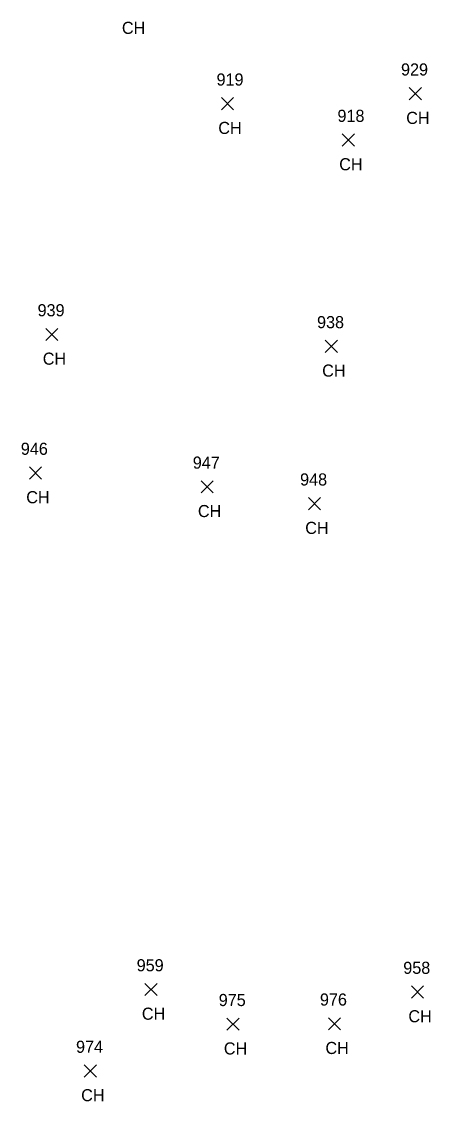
# Model space of a CAD drawing. Extents: x 1885914 to 1887218, y 756253 to 760620.
# Drawn here: x 1886670.4 to 1886738.1, y 759584.2 to 759762.6 of the extents above; entities that cross this region are included whole.
import ezdxf

# ---------------------------------------------------------------- set-up
doc = ezdxf.new("R2010")
doc.units = 0
for name, color, linetype in [('L_A', 7, 'Continuous'), ('L_I', 7, 'Continuous'), ('L_TIC', 7, 'Continuous')]:
    doc.layers.add(name, color=color, linetype=linetype)

msp = doc.modelspace()

# ---------------------------------------------------------------- linework, layer by layer
at = {"layer": 'L_TIC'}
for points in [[(1886734.56, 759749.69), (1886736.56, 759751.69)], [(1886736.56, 759749.69), (1886734.56, 759751.69)], [(1886703.49, 759748.03), (1886705.49, 759750.03)], [(1886705.49, 759748.03), (1886703.49, 759750.03)], [(1886723.48, 759742.03), (1886725.48, 759744.03)], [(1886725.48, 759742.03), (1886723.48, 759744.03)], [(1886674.45, 759709.92), (1886676.45, 759711.92)], [(1886676.45, 759709.92), (1886674.45, 759711.92)], [(1886720.66, 759707.95), (1886722.66, 759709.95)], [(1886722.66, 759707.95), (1886720.66, 759709.95)], [(1886671.72, 759687.04), (1886673.72, 759689.04)], [(1886673.72, 759687.04), (1886671.72, 759689.04)], [(1886700.12, 759684.75), (1886702.12, 759686.75)], [(1886702.12, 759684.75), (1886700.12, 759686.75)], [(1886717.87, 759681.97), (1886719.87, 759683.97)], [(1886719.87, 759681.97), (1886717.87, 759683.97)], [(1886690.84, 759601.73), (1886692.84, 759603.73)], [(1886692.84, 759601.73), (1886690.84, 759603.73)], [(1886734.92, 759601.31), (1886736.92, 759603.31)], [(1886736.92, 759601.31), (1886734.92, 759603.31)], [(1886704.4, 759595.99), (1886706.4, 759597.99)], [(1886706.4, 759595.99), (1886704.4, 759597.99)], [(1886721.2, 759596.07), (1886723.2, 759598.07)], [(1886723.2, 759596.07), (1886721.2, 759598.07)], [(1886680.8, 759588.27), (1886682.8, 759590.27)], [(1886682.8, 759588.27), (1886680.8, 759590.27)]]:
    msp.add_lwpolyline(points, dxfattribs=at)

# ---------------------------------------------------------------- texts
at = {"layer": 'L_A'}
for p in [(1886687.03, 759760.56), (1886734.05, 759745.69), (1886702.97, 759744.03), (1886722.97, 759738.03), (1886673.94, 759705.92), (1886720.15, 759703.95), (1886671.21, 759683.04), (1886699.6, 759680.75), (1886717.35, 759677.97), (1886690.33, 759597.73), (1886734.41, 759597.31), (1886703.89, 759591.99), (1886720.69, 759592.07), (1886680.29, 759584.27)]:
    msp.add_text('CH', height=2, dxfattribs=at).set_placement(p)
at = {"layer": 'L_I'}
for s, p in [('929', (1886733.19, 759753.69)), ('919', (1886702.68, 759752.03)), ('918', (1886722.68, 759746.03)), ('939', (1886673.08, 759713.92)), ('938', (1886719.3, 759711.95)), ('946', (1886670.31, 759691.04)), ('947', (1886698.75, 759688.75)), ('948', (1886716.5, 759685.97)), ('959', (1886689.47, 759605.73)), ('958', (1886733.56, 759605.31)), ('975', (1886703.04, 759599.99)), ('976', (1886719.78, 759600.07)), ('974', (1886679.44, 759592.27))]:
    msp.add_text(s, height=2, dxfattribs=at).set_placement(p)

doc.saveas('drawing.dxf')
